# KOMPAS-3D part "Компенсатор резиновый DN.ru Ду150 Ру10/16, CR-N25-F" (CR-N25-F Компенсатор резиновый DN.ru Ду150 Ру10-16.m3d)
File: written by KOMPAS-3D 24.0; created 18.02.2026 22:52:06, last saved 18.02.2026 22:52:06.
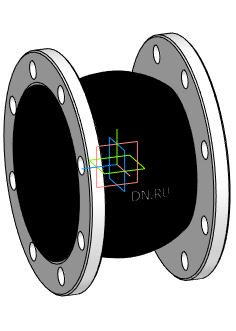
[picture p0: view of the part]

Document properties: Автор: DN.RU; Полное имя файла: D:\PROJECT CAD\DN.RU\...178(1)(ACTUALE). CR-N25-F Компенсатор резиновый DN.ru Ру10-16\DN150\CR-N25-F Компенсатор резиновый DN.ru Ду150 Ру10-16.m3d

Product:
- Body: Твердое тело2  | qty 1
    Масса: 29.199535
- Part/product: Компенсатор резиновый DN.ru Ду150 Ру10/16  | designation CR-N25-F
    Масса: 15
    Раздел спецификации: Прочие изделия
    Комментарий: D140-02396
    Примечание: D140-02396
    additional columns: Типовые

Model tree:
1. Твердое тело2  (labels: Твердое тело2)

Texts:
  CR-N25-F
